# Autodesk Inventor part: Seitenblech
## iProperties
Created: 2006-10
Part Number: Seitenblech
Document SubType Name: Modeling
Designer: Robert Hüttner
Author: Robert Hüttner
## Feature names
1. Trennen1
